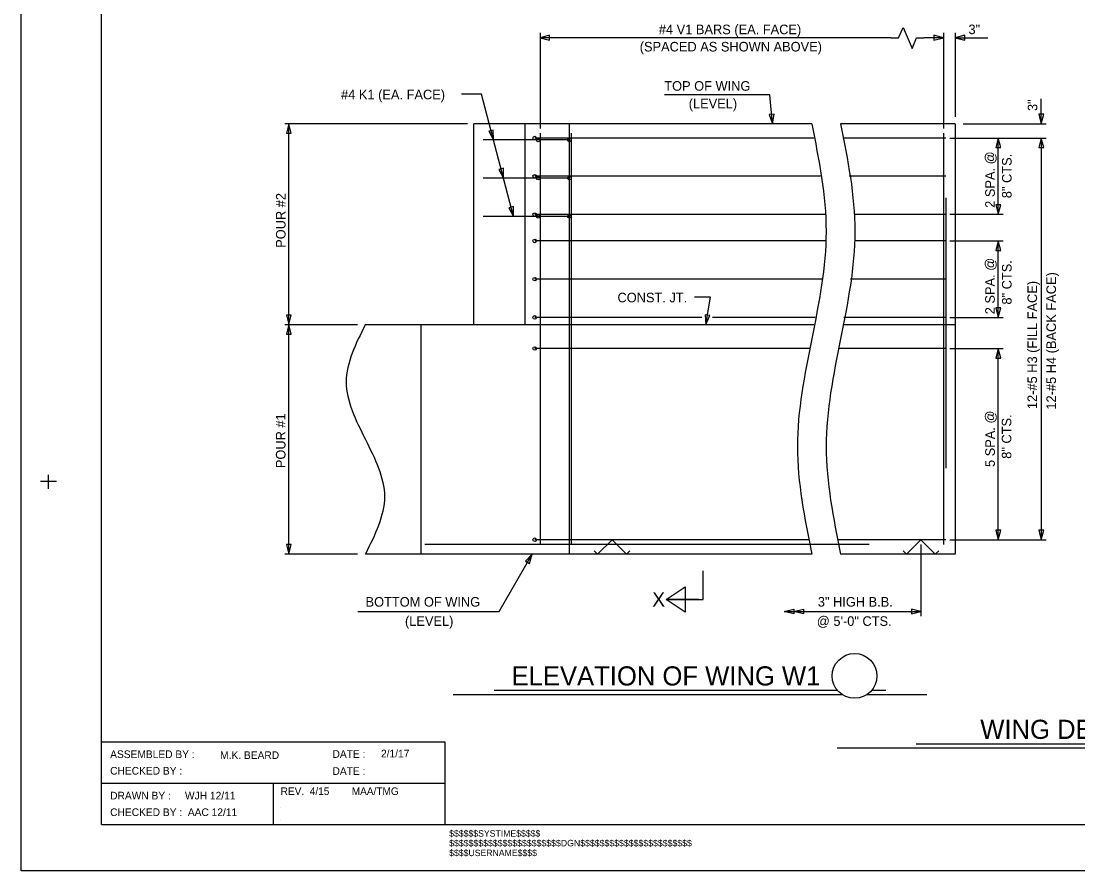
# Model space of a CAD drawing. Extents: x -41 to 191, y -168 to 6.
# Drawn here: x 0 to 18.42, y -98.82 to -84.01 of the extents above; entities that cross this region are included whole.
import ezdxf

# ---------------------------------------------------------------- set-up
doc = ezdxf.new("R2010")
doc.units = 0
for name, color, linetype in [('Arrowhead Terminators CELL', 7, 'Continuous'), ('Beam Bolsters CELL', 7, 'Continuous'), ('Default', 7, 'Continuous'), ('Dimension Lines', 7, 'Continuous'), ('Mis Object Lines', 7, 'Continuous'), ('Mis Object Lines Hidden', 7, 'Continuous'), ('Plan Sheet', 7, 'Continuous'), ('Plan Sheet CELL', 7, 'Continuous'), ('Plot Label CELL', 7, 'Continuous'), ('Plot Shape CELL', 7, 'Continuous'), ('Rebar K Bar Lines', 7, 'Continuous'), ('Rebar Lines', 7, 'Continuous'), ('Subtitle Text', 7, 'Continuous'), ('Text', 7, 'Continuous'), ('Title Text', 7, 'Continuous'), ('User Information Notes', 7, 'Continuous'), ('User Information Notes CELL', 7, 'Continuous')]:
    doc.layers.add(name, color=color, linetype=linetype)

# ---------------------------------------------------------------- blocks, each defined once
blk = doc.blocks.new('3 HIGH BEAM BOLSTER')
at = {"layer": 'Default'}
blk.add_lwpolyline([(-0.31, -0.192), (-0.251, -0.251), (0, 0), (0.251, -0.251), (0.31, -0.192)], dxfattribs=at)
blk = doc.blocks.new('SECSYM')
at = {"layer": 'Arrowhead Terminators CELL'}
blk.add_lwpolyline([(0, 0), (-2.48, 1.65), (-2.48, -1.65)], close=True, dxfattribs=at)

msp = doc.modelspace()

# ---------------------------------------------------------------- linework, layer by layer
at = {"layer": 'Arrowhead Terminators CELL'}
for points in [[(9.046, -84.302), (9.213, -84.343), (9.213, -84.26)], [(16.076, -84.302), (15.91, -84.26), (15.91, -84.343)], [(16.283, -84.302), (16.45, -84.343), (16.45, -84.26)], [(13.1, -85.802), (13.125, -85.632), (13.042, -85.64)], [(17.783, -85.802), (17.825, -85.635), (17.742, -85.635)], [(4.668, -85.802), (4.626, -85.968), (4.709, -85.968)], [(8.233, -86.083), (8.231, -85.912), (8.151, -85.933)], [(17.033, -86.052), (16.992, -86.218), (17.075, -86.218)], [(17.783, -86.052), (17.742, -86.218), (17.825, -86.218)], [(8.408, -86.75), (8.406, -86.578), (8.326, -86.599)], [(8.583, -87.416), (8.581, -87.245), (8.501, -87.266)], [(17.033, -87.379), (17.075, -87.212), (16.992, -87.212)], [(17.033, -87.843), (16.992, -88.01), (17.075, -88.01)], [(4.668, -89.302), (4.709, -89.135), (4.626, -89.135)], [(11.936, -89.302), (12.005, -89.145), (11.923, -89.131)], [(17.033, -89.177), (17.075, -89.01), (16.992, -89.01)], [(4.668, -89.302), (4.626, -89.468), (4.709, -89.468)], [(17.033, -89.718), (16.992, -89.885), (17.075, -89.885)], [(17.033, -93.052), (17.075, -92.885), (16.992, -92.885)], [(17.783, -93.052), (17.825, -92.885), (17.742, -92.885)], [(4.668, -93.302), (4.709, -93.135), (4.626, -93.135)], [(8.908, -93.302), (8.789, -93.425), (8.861, -93.466)], [(13.302, -94.302), (13.468, -94.26), (13.468, -94.343)], [(13.468, -94.302), (13.635, -94.26), (13.635, -94.343)], [(15.684, -94.302), (15.518, -94.26), (15.518, -94.343)]]:
    msp.add_lwpolyline(points, close=True, dxfattribs=at)
at = {"layer": 'Beam Bolsters CELL'}
msp.add_lwpolyline([(15.374, -93.243), (15.433, -93.302), (15.684, -93.052), (15.935, -93.302), (15.994, -93.243)], dxfattribs=at)
at = {"layer": 'Default'}
msp.add_lwpolyline([(15.167, -84.302), (15.295, -84.302), (15.377, -84.123), (15.531, -84.489), (15.608, -84.302), (15.739, -84.302)], dxfattribs=at)
at = {"layer": 'Dimension Lines'}
for p, q in [((9.046, -84.218), (9.046, -85.885)), ((15.167, -84.302), (9.046, -84.302)), ((16.076, -84.302), (15.739, -84.302)), ((16.076, -84.218), (16.076, -85.885)), ((16.283, -84.218), (16.283, -85.679)), ((16.283, -84.302), (16.848, -84.302)), ((8.024, -85.287), (7.679, -85.287)), ((8.583, -87.416), (8.024, -85.287)), ((13.05, -85.299), (11.217, -85.299)), ((13.1, -85.802), (13.05, -85.299)), ((17.783, -85.802), (17.783, -85.37)), ((7.78, -85.802), (4.597, -85.802)), ((4.668, -89.302), (4.668, -85.802)), ((16.423, -85.802), (17.867, -85.802)), ((16.189, -86.052), (17.867, -86.052)), ((17.033, -87.379), (17.033, -86.052)), ((17.783, -86.052), (17.783, -93.052)), ((16.189, -87.379), (17.117, -87.379)), ((16.189, -87.843), (17.117, -87.843)), ((17.033, -89.177), (17.033, -87.843)), ((12.017, -88.825), (11.736, -88.825)), ((11.936, -89.302), (12.017, -88.825)), ((4.597, -89.302), (5.866, -89.302)), ((4.668, -93.302), (4.668, -89.302)), ((16.189, -89.177), (17.117, -89.177)), ((16.189, -89.718), (17.117, -89.718)), ((17.033, -93.052), (17.033, -89.718)), ((15.684, -93.135), (15.684, -94.385)), ((16.189, -93.052), (17.867, -93.052)), ((5.866, -93.302), (4.597, -93.302)), ((11.888, -94.094), (11.888, -93.594)), ((11.81, -94.094), (11.245, -94.094)), ((11.245, -94.094), (11.888, -94.094)), ((13.302, -94.302), (15.684, -94.302))]:
    msp.add_line(p, q, dxfattribs=at)
msp.add_lwpolyline([(5.868, -94.302), (8.331, -94.302), (8.908, -93.302)], dxfattribs=at)
for points in [[(13.781, -85.802), (14.031, -87.677), (13.781, -89.552), (13.531, -91.427), (13.781, -93.302)], [(14.283, -85.802), (14.533, -87.677), (14.283, -89.552), (14.033, -91.427), (14.283, -93.302)]]:
    msp.add_spline(points, degree=3, dxfattribs=at)
at = {"layer": 'Mis Object Lines'}
for p, q in [((13.781, -85.802), (7.889, -85.802)), ((7.889, -89.302), (7.889, -85.802)), ((8.785, -89.302), (8.785, -85.802)), ((16.283, -85.802), (14.283, -85.802)), ((16.283, -85.802), (16.283, -93.302)), ((6, -89.302), (8.785, -89.302)), ((6.972, -93.302), (6.972, -89.302)), ((13.781, -93.302), (6, -93.302)), ((16.283, -93.302), (14.283, -93.302))]:
    msp.add_line(p, q, dxfattribs=at)
msp.add_spline([(6, -89.302), (5.666, -90.302), (6, -91.302), (6.333, -92.302), (6, -93.302)], degree=3, dxfattribs=at)
at = {"layer": 'Mis Object Lines Hidden'}
for p, q in [((9.551, -85.802), (9.551, -93.302)), ((8.785, -89.302), (13.819, -89.302)), ((14.321, -89.302), (16.283, -89.302))]:
    msp.add_line(p, q, dxfattribs=at)
at = {"layer": 'Plan Sheet CELL'}
for p, q in [((1.402, -98.017), (1.402, -70.087)), ((0.339, -92.032), (0.619, -92.032)), ((0.475, -92.163), (0.475, -91.923)), ((1.402, -96.574), (7.387, -96.574)), ((7.387, -96.574), (7.387, -97.296)), ((1.402, -97.296), (7.387, -97.296)), ((4.394, -97.296), (4.394, -98.017)), ((7.387, -97.296), (7.387, -98.017)), ((1.402, -98.017), (43.962, -98.017)), ((0, -98.823), (0, -98.823))]:
    msp.add_line(p, q, dxfattribs=at)
at = {"layer": 'Plot Shape CELL'}
msp.add_lwpolyline([(0, -69.563), (43.974, -69.563), (43.974, -98.823), (0, -98.823)], close=True, dxfattribs=at)
at = {"layer": 'Rebar K Bar Lines'}
for centre in [(9.014, -86.083), (9.556, -86.083), (9.014, -86.75), (9.556, -86.75), (9.014, -87.416), (9.556, -87.416)]:
    msp.add_circle(centre, 0.0312, dxfattribs=at)
at = {"layer": 'Rebar Lines'}
for p, q in [((9.046, -85.968), (9.046, -93.135)), ((9.59, -85.968), (9.59, -93.135)), ((16.076, -85.968), (16.076, -93.135)), ((9.556, -86.083), (8.055, -86.083)), ((13.819, -86.052), (8.952, -86.052)), ((16.117, -86.052), (14.321, -86.052)), ((9.556, -86.75), (8.055, -86.75)), ((13.934, -86.718), (8.952, -86.718)), ((16.117, -86.718), (14.436, -86.718)), ((9.556, -87.416), (8.055, -87.416)), ((14.02, -87.385), (8.952, -87.385)), ((16.117, -87.385), (14.522, -87.385)), ((14.028, -87.843), (8.952, -87.843)), ((16.117, -87.843), (14.53, -87.843)), ((13.955, -88.51), (8.952, -88.51)), ((16.117, -88.51), (14.457, -88.51)), ((11.865, -89.177), (8.952, -89.177)), ((13.839, -89.177), (12.053, -89.177)), ((16.117, -89.177), (14.341, -89.177)), ((13.757, -89.718), (8.952, -89.718)), ((16.117, -89.718), (14.259, -89.718)), ((13.744, -93.052), (8.952, -93.052)), ((16.117, -93.052), (14.246, -93.052))]:
    msp.add_line(p, q, dxfattribs=at)
for centre in [(8.952, -86.052), (8.952, -86.718), (8.952, -87.385), (8.952, -87.843), (8.952, -88.51), (8.952, -89.177), (8.952, -89.718), (8.952, -93.052)]:
    msp.add_circle(centre, 0.0312, dxfattribs=at)
at = {"layer": 'Title Text'}
for p, q in [((7.532, -95.75), (14.313, -95.75)), ((8.244, -95.676), (14.229, -95.676)), ((14.742, -95.75), (15.786, -95.75)), ((14.825, -95.676), (15.074, -95.676)), ((14.226, -96.681), (22.963, -96.681)), ((14.89, -96.681), (21.67, -96.681)), ((15.601, -96.607), (21.587, -96.607))]:
    msp.add_line(p, q, dxfattribs=at)
msp.add_circle((14.527, -95.425), 0.39, dxfattribs=at)
at = {"layer": 'User Information Notes'}
for p, q in [((4.524, -97.49), (4.524, -97.49)), ((4.524, -97.72), (4.524, -97.72)), ((4.524, -97.94), (4.524, -97.94))]:
    msp.add_line(p, q, dxfattribs=at)
at = {"layer": 'User Information Notes CELL'}
for p, q in [((16.117, -87.092), (16.117, -91.802)), ((14.785, -93.135), (7.035, -93.135))]:
    msp.add_line(p, q, dxfattribs=at)

# ---------------------------------------------------------------- block references
at = {"layer": 'Dimension Lines', "xscale": 0.1331292, "yscale": -0.133130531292, "rotation": 180}
msp.add_blockref('SECSYM', (11.245, -94.094), dxfattribs=at)
at = {"layer": 'Rebar Lines', "yscale": -1.00001, "rotation": 180}
msp.add_blockref('3 HIGH BEAM BOLSTER', (10.3, -93.052), dxfattribs=at)

# ---------------------------------------------------------------- texts
at = {"layer": 'Plan Sheet'}
msp.add_text('REV.  4/15        MAA/TMG', height=0.13124, dxfattribs=at).set_placement((4.524, -97.5))
at = {"layer": 'Plan Sheet CELL'}
for s, height, p in [('ASSEMBLED BY :', 0.13299, (1.552, -96.857)), ('DATE :', 0.133, (5.428, -96.853)), ('CHECKED BY :', 0.13299, (1.552, -97.145)), ('DATE :', 0.133, (5.428, -97.15)), ('DRAWN BY :     WJH 12/11', 0.13299, (1.552, -97.578)), ('CHECKED BY :  AAC 12/11', 0.13299, (1.552, -97.867))]:
    msp.add_text(s, height=height, dxfattribs=at).set_placement(p)
at = {"layer": 'Plot Label CELL'}
for s, height, p in [('$$$$$$SYSTIME$$$$$', 0.1131, (7.461, -98.227)), ('$$$$$$$$$$$$$$$$$$$$$$$DGN$$$$$$$$$$$$$$$$$$$$$$$', 0.11379, (7.461, -98.396)), ('$$$$USERNAME$$$$', 0.1131, (7.461, -98.566))]:
    msp.add_text(s, height=height, dxfattribs=at).set_placement(p)
at = {"layer": 'Subtitle Text'}
msp.add_text('X', height=0.25, dxfattribs=at).set_placement((11.001, -94.218))
at = {"layer": 'Text'}
for s, rotation, p in [('#4 V1 BARS (EA. FACE)', 360, (11.116, -84.241)), ('3"', 360, (16.513, -84.24)), ('TOP OF WING', 360, (11.211, -85.226)), ('#4 K1 (EA. FACE)', 360, (5.577, -85.376)), ('(LEVEL)', 360, (11.637, -85.533)), ('3"', 90, (17.714, -85.58)), ('2 SPA. @', 90, (16.972, -87.267)), ('8" CTS.', 90, (17.265, -87.099)), ('POUR #2', 90, (4.609, -87.964)), ('2 SPA. @', 90, (16.972, -89.122)), ('8" CTS.', 90, (17.265, -88.953)), ('12-#5 H4 (BACK FACE)', 90, (18.039, -90.784)), ('12-#5 H3 (FILL FACE)', 90, (17.709, -90.775)), ('CONST. JT.', 360, (10.395, -88.914)), ('POUR #1', 90, (4.608, -91.804)), ('5 SPA. @', 90, (16.973, -91.784)), ('8" CTS.', 90, (17.261, -91.641))]:
    msp.add_text(s, height=0.167, rotation=rotation, dxfattribs=at).set_placement(p)
for s, p in [(' (SPACED AS SHOWN ABOVE)', (10.721, -84.542)), ('BOTTOM OF WING', (6.004, -94.218)), ('3" HIGH B.B.', (13.887, -94.218)), ('(LEVEL)', (6.691, -94.553)), ('@ 5\'-0" CTS.', (13.87, -94.553))]:
    msp.add_text(s, height=0.167, dxfattribs=at).set_placement(p)
at = {"layer": 'Title Text'}
for s, height, p in [('ELEVATION OF WING W1', 0.33388, (8.549, -95.592)), ('WING DETAILS', 0.33388, (16.719, -96.523)), ('2/1/17', 0.133, (6.273, -96.845)), ('M.K. BEARD', 0.133, (3.469, -96.873))]:
    msp.add_text(s, height=height, dxfattribs=at).set_placement(p)

doc.saveas('drawing.dxf')
